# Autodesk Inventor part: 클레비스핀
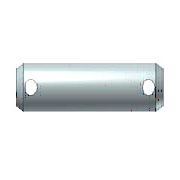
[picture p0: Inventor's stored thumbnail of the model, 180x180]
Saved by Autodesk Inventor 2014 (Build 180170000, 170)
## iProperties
Created: 2012-02
Part Number: 클레비스핀
Material: 강철
Description: 머리가 없는 클레비스 핀 B
Document SubType Name: Modeling
Standard: ISO 2340
Designer: mduedu
Standard Revision: Second edition 1986-11-01
Standards Organization: ISO
Language: ko-KR
Size Designation: B - 8 x 45
Categories: <MemberInstance><Categories><Category DisplayName="조임쇠" InternalName="e4da775c-781d-43d5-af7c-5136215cf5a6" Mnemonic="FSTN"><Category DisplayName="핀" InternalNa
Density: 7.85 g/cm^3
Appearance: 강철
IsCustomPart: 1
Author: mduedu
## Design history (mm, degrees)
sketch "스케치1"
  geometry: L1 (-4.5, 0)-(-4.5, 4); L2 (-4.5, 4)-(40.5, 4); L3 (40.5, 4)-(40.5, 0); L4 (-4.5, 0)-(40.5, 0); L5 (0, -1.46)-(0, 3.16) reference; L6 (-6.4, 0)-(18.8, 0) reference; C1 r 1 at (-1, 0); C2 r 1 at (37, 0)
  constraints: 8 end point, 2 centre point, 2 perpendicular, 2 point on line, 1 collinear, 1 parallel, 1 tangent, 1 vertical
  dimensions: "d0" = 8 diameter of L2 L4 (= NND); "d1" = 45 distance of L1.end L2.end (= NLG); "d2" = 3.5 distance from line of L1 C1.centre (= DIST1); "d3" = 3.5 distance from line of L3 C2.centre (= DIST2); "d4" = 2 diameter of C1 (= BOR1); "d5" = 2 diameter of C2 (= BOR2)
revolve "본체" stored, may be unused: angle "d7" = 90 deg
extrude "구멍1" cut sketch "스케치1" taper "d6" = 0 deg; stored distance "d8" = 10
extrude "구멍2" cut sketch "스케치1" taper "d13" = 0 deg; stored distance "d14" = 10
workaxis "Work Axis1"
workaxis "Work Axis2"
workplane "Work Plane1"
node "작업 평면5"
body "Solid1"
chamfer "모따기2" distance "d9" = 2 (= PHH2); stored, may be unused: angle "d10" = 30 deg (= FAWI2), second distance "d40" = 2 (= PHH2)
chamfer "모따기1" distance "d11" = 2 (= PHH1); stored, may be unused: angle "d12" = 30 deg (= FAWI1), second distance "d41" = 2 (= PHH1)
other parameters: "NLG" = 45 [user parameter; used in 1 equation term], "NND" = 8 [user parameter; used in 1 equation term], "PHH1" = 2 [user parameter; used in 3 equation terms], "PHH2" = 2 (= PHH1) [user parameter; used in 2 equation terms], "FAWI1" = 30 deg [user parameter; used in 1 equation term], "FAWI2" = 30 deg [user parameter; used in 1 equation term], "DIST1" = 3.5 [user parameter; used in 4 equation terms], "DIST2" = 3.5 (= DIST1) [user parameter; used in 1 equation term], "BOR1" = 2 [user parameter; used in 4 equation terms], "BOR2" = 2 (= BOR1) [user parameter; used in 1 equation term], "d15" = 0, "d42" = 0, "d43" = 0, "d44" = -4.5 (= -0.5 x BOR1 - DIST1), "d45" = -4.5 (= -0.5 x BOR1 - DIST1), "d47" = 0, "d48" = 0, "d49" = 0, "d50" = 0, "d51" = 0, "d52" = 0
